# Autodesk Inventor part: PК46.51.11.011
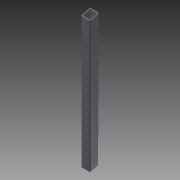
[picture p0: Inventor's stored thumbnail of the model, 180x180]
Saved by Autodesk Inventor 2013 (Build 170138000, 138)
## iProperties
Shininess: 64.0
Length Units: 11269
Angle Units: 11279
Time Units: 11290
Mass Units: 11283
Length Display Precision: 3
Angle Display Precision: 2
Compacted: True
Part Number: PК46.51.11.011
Document SubType Name: Modeling
Created: 2004-07
Material: Steel, Mild
Designer: =<Author>
Manufacturer: Standard
Standards Organization: Custom
Description: pipe
Density: 7.86 g/cm^3
Mass: 689.222 g
Surface Area: 884.525 cm^2
Volume: 87.6872 cm^3
Density: 0.0
Volumn: 0.0
Area: 0.0
PropertySet Name: Model Information
Control State: 0
Master: False
Checked Out: False
Checked Out Date: 2008-10-15
Last Check In Date: 2008-10-15
Author: PVitaliy
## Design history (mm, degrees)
sketch "Эскиз1"
  geometry: L1 (4, 0)-(26, 0); L2 (30, 4)-(30, 26); L3 (26, 30)-(4, 30); L4 (0, 26)-(0, 4); L5 (2, 26)-(2, 4); L6 (4, 2)-(26, 2); L7 (28, 4)-(28, 26); L8 (26, 28)-(4, 28); A1 r 4 centre (4, 26) between (4, 30) and (0, 26); A2 r 4 centre (26, 26) between (30, 26) and (26, 30); A3 r 4 centre (26, 4) between (26, 0) and (30, 4); A4 r 4 centre (4, 4) between (0, 4) and (4, 0); A5 r 2 centre (4, 26) between (4, 28) and (2, 26); A6 r 2 centre (4, 4) between (2, 4) and (4, 2); A7 r 2 centre (26, 4) between (26, 2) and (28, 4); A8 r 2 centre (26, 26) between (28, 26) and (26, 28); 3 further points
  constraints: 16 end point, 16 point on circle, 8 centre point, 8 tangent, 6 point on line, 4 parallel, 2 equal radius, 2 perpendicular, 1 horizontal, 8 other
  dimensions: "d0" = 30 distance of point (0, 30) point (0, 0); "d1" = 30 distance of point (0, 0) point (30, 0); "d2" = 4 radius of A1; "d3" = 4 radius of A2; "d4" = 2 distance between parallel lines of L1 L6
extrude "Выдавливание1" new body sketch "Эскиз1" distance "d5" = 442; taper "d6" = 0 deg
sketch "Эскиз2"
  geometry: L1 (442, 0)-(442, 22) reference; L2 (0, -4)-(442, -4) reference; L3 (442, 0)-(442, -4) reference; L4 (0, 26)-(442, 26) reference; L5 (442, 26)-(442, 22) reference; L6 (442, 26)-(433.962, -4); L7 (0, 22)-(0, 0) reference; L8 (0, -4)-(0, 0) reference; L9 (0, 22)-(0, 26) reference; L10 (0, -4)-(8.038, 26)
  constraints: 4 end point, 2 point on line
  dimensions: "d7" = 15 deg angle of L1 L6; "d10" = 15 deg angle of L10 L7
extrude "Выдавливание2" cut sketch "Эскиз2" stored distance "d8" = 10; taper "d9" = 0 deg
sketch "Эскиз3"
  geometry: L1 (5.895, 22)-(439.856, 22) reference; L2 (6.967, 26)-(440.928, 26) reference; L3 (-1.072, -4)-(432.89, -4) reference; L4 (-1.072, -4)-(0, 0) reference; L5 (5.895, 22)-(6.967, 26) reference; L6 (5.895, 22)-(86.967, 22); L7 (86.967, 22)-(86.967, 26)
  constraints: 4 end point, 2 point on line, 1 perpendicular
  dimensions: "d11" = 80 distance from line of L2.start L7
extrude "Выдавливание3" cut sketch "Эскиз3" stored distance "d12" = 10; taper "d13" = 0 deg
body "Solid1"
